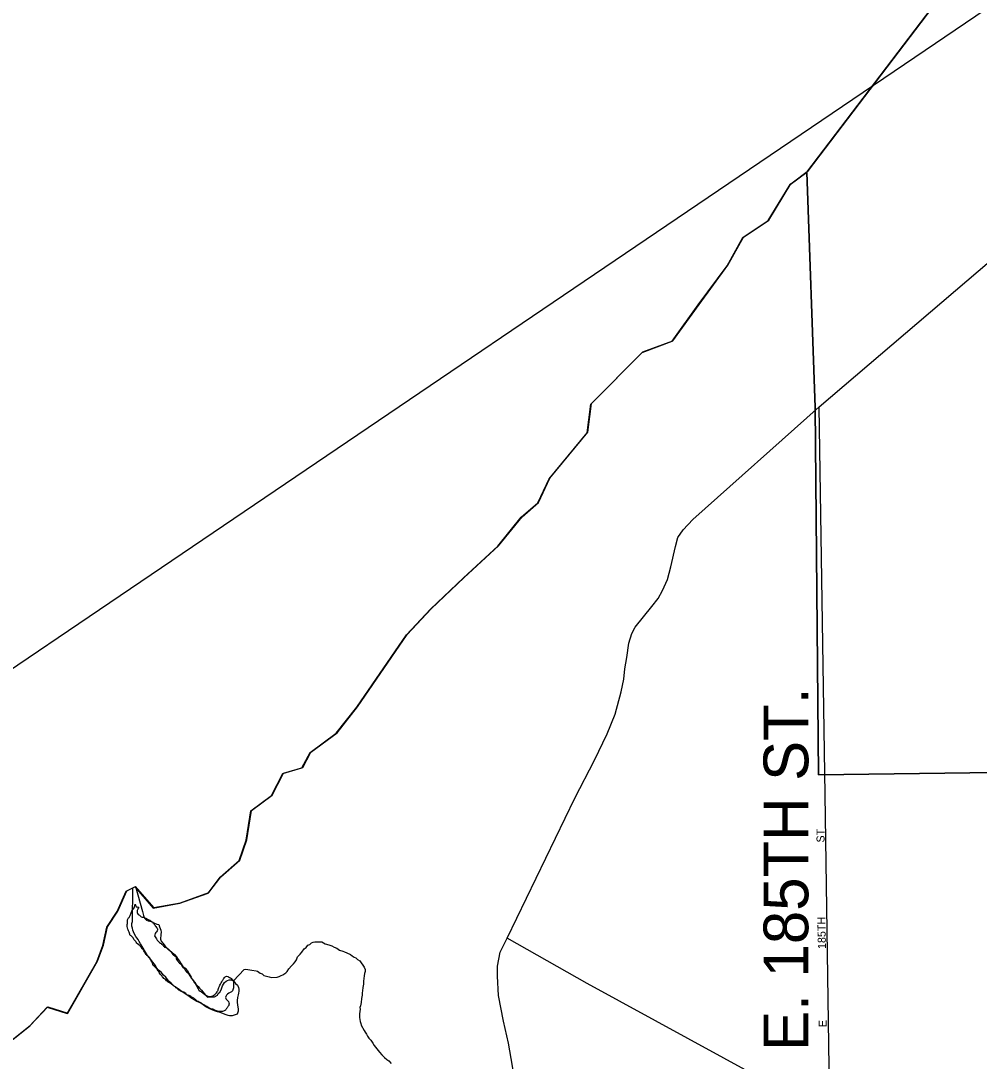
# Model space of a CAD drawing. Extents: x 2139079 to 2262683, y 1235796 to 1334992.
# Drawn here: x 2223564 to 2229551, y 1307072 to 1313569 of the extents above; entities that cross this region are included whole.
import ezdxf

# ---------------------------------------------------------------- set-up
doc = ezdxf.new("R2010")
doc.units = 0
for name, color, linetype in [('GM_X_City_Street', 7, 'Continuous'), ('GM_X_City_Street_Text', 7, 'Continuous'), ('GM_X_Interchange_Ramps', 7, 'Continuous'), ('GM_X_Interstate_Route', 7, 'Continuous'), ('GM_X_Major_Lake', 7, 'Continuous'), ('GM_X_Major_River', 7, 'Continuous'), ('GM_X_Minor_Lake', 7, 'Continuous'), ('GM_X_Minor_River', 7, 'Continuous'), ('GM_X_State_Route', 7, 'Continuous'), ('GM_X_US_Route', 7, 'Continuous')]:
    doc.layers.add(name, color=color, linetype=linetype)

msp = doc.modelspace()

# ---------------------------------------------------------------- linework, layer by layer
at = {"layer": 'GM_X_City_Street'}
for points in [[(2228588, 1308737.8), (2228551.1, 1311159.1)], [(2228627.4, 1305337.6), (2228622.6, 1306468.3), (2228588, 1308737.8)], [(2229151.8, 1305804), (2228622.6, 1306468.3), (2228218.5, 1306943.9), (2228158.5, 1306979.9), (2227102.5, 1307556.5), (2226602.2, 1307841.3)]]:
    msp.add_lwpolyline(points, dxfattribs=at)
at = {"layer": 'GM_X_Interstate_Route'}
for points in [[(2231225.8, 1308895.9), (2228546, 1308860.7), (2228526.3, 1311154.9), (2228474.5, 1312624.7), (2229502.7, 1313976.8)], [(2231225.8, 1308895.9), (2228546, 1308860.7), (2228526.3, 1311154.9), (2228474.5, 1312624.7), (2229502.7, 1313976.8)], [(2223516.6, 1307210.2), (2223618.1, 1307291.6), (2223729.2, 1307409.2), (2223854.1, 1307370.3), (2224039.3, 1307693.4), (2224076.3, 1307794.2), (2224101.2, 1307908.8), (2224166.3, 1308005.9), (2224223.2, 1308132.9), (2224276.7, 1308160.4), (2224390.9, 1308028.3), (2224557.1, 1308058.2), (2224735.1, 1308122.3), (2224810.3, 1308221.4), (2224927.6, 1308325), (2224972.3, 1308451.9), (2225000.5, 1308634.9), (2225129.9, 1308730.6), (2225200.7, 1308867.8), (2225320.7, 1308903.2), (2225371.8, 1309000.1), (2225535.1, 1309120.2), (2225663.8, 1309282.1), (2225974, 1309735), (2226122.8, 1309895.1), (2226329.4, 1310089.9), (2226544, 1310288.9), (2226690.6, 1310469.1), (2226794, 1310558.5), (2226864.6, 1310709.7), (2227102.4, 1310997.2), (2227124.5, 1311176.1), (2227446.2, 1311498.6), (2227632.1, 1311568.8), (2227796.2, 1311795.3), (2227976.2, 1312040), (2228074.7, 1312215.7), (2228232.1, 1312321.7), (2228370.1, 1312547.9), (2228474.5, 1312624.7), (2228526.3, 1311154.9), (2228546, 1308860.7), (2231225.8, 1308895.9)]]:
    msp.add_lwpolyline(points, dxfattribs=at)
at = {"layer": 'GM_X_Major_Lake'}
for points in [[(2224395.3, 1308030.9), (2224561.6, 1308060.8), (2224739.5, 1308124.9), (2224814.7, 1308224), (2224932, 1308327.6), (2224976.8, 1308454.6), (2225004.9, 1308637.5), (2225134.3, 1308733.2), (2225205.1, 1308870.4), (2225325.1, 1308905.8), (2225376.3, 1309002.7), (2225539.6, 1309122.8), (2225668.3, 1309284.7), (2225978.5, 1309737.6), (2226127.3, 1309897.7), (2226333.9, 1310092.6), (2226548.5, 1310291.5), (2226695.1, 1310471.7), (2226798.5, 1310561.1), (2226869.1, 1310712.3), (2227106.8, 1310999.8), (2227129, 1311178.7), (2227450.6, 1311501.2), (2227636.5, 1311571.4), (2227800.6, 1311797.9), (2227980.7, 1312042.7), (2228079.1, 1312218.3), (2228236.5, 1312324.3), (2228374.6, 1312550.6), (2228484, 1312634), (2229507.2, 1313979.4)], [(2223397.7, 1307113.2), (2223521.1, 1307212.8), (2223622.6, 1307294.2), (2223733.7, 1307411.8), (2223858.5, 1307372.9), (2224043.7, 1307696.1), (2224080.7, 1307796.8), (2224105.6, 1307911.5), (2224170.8, 1308008.5), (2224227.6, 1308135.5), (2224281.1, 1308163)], [(2224395.3, 1308030.9), (2224281.1, 1308163)]]:
    msp.add_lwpolyline(points, dxfattribs=at)
at = {"layer": 'GM_X_Major_River'}
for p, q in [((2224278.3, 1308052.4), (2224282.5, 1308040.1)), ((2224282.5, 1308040.1), (2224286, 1308037)), ((2224286, 1308037), (2224289.3, 1308035.2)), ((2224289.3, 1308035.2), (2224294.6, 1308034.1)), ((2224294.6, 1308034.1), (2224302.5, 1308034.6))]:
    msp.add_line(p, q, dxfattribs=at)
for points in [[(2224282.4, 1307819.6), (2224268.2, 1307837.6), (2224262.1, 1307847.6), (2224245.9, 1307861.5), (2224243.8, 1307871.5), (2224237.7, 1307885.5), (2224233.6, 1307897.5), (2224229.5, 1307913.5), (2224229.3, 1307925.6), (2224231.2, 1307939.6), (2224231.1, 1307949.7), (2224233.1, 1307959.7), (2224242.9, 1307973.9), (2224250.8, 1307992), (2224256.7, 1308004.1), (2224260.6, 1308014.2), (2224268.5, 1308024.3), (2224274.5, 1308036.4), (2224278.3, 1308052.4)], [(2224302.5, 1308034.6), (2224290.7, 1308006.4), (2224292.9, 1307994.3), (2224305, 1307984.4), (2224317.1, 1307974.5), (2224329.1, 1307970.6), (2224349.2, 1307962.7), (2224363.3, 1307954.8), (2224375.4, 1307948.8), (2224389.5, 1307936.9), (2224401.6, 1307923), (2224407.7, 1307913), (2224418, 1307891), (2224412, 1307880.9), (2224404.1, 1307868.8), (2224400.2, 1307854.7), (2224408.4, 1307842.7), (2224416.5, 1307828.7), (2224424.6, 1307818.8), (2224436.7, 1307808.8), (2224450.8, 1307796.9), (2224462.9, 1307784.9), (2224477, 1307779), (2224487.1, 1307767.1)], [(2224487.1, 1307767.1), (2224501.3, 1307757.1), (2224509.4, 1307745.1), (2224521.5, 1307731.2), (2224535.6, 1307721.3), (2224535.7, 1307711.2), (2224543.8, 1307699.2), (2224556, 1307683.3), (2224566.1, 1307675.3), (2224574.2, 1307661.4), (2224586.3, 1307649.4), (2224596.5, 1307633.4), (2224608.6, 1307623.5), (2224628.9, 1307591.5), (2224641, 1307577.6), (2224645.1, 1307567.6), (2224655.3, 1307553.6), (2224663.4, 1307539.6), (2224683.7, 1307509.7), (2224693.8, 1307503.7), (2224707.9, 1307491.8), (2224724, 1307481.9), (2224740.1, 1307476), (2224756.1, 1307478.1), (2224770.1, 1307484.3), (2224789.9, 1307504.5), (2224797.8, 1307520.6), (2224801.7, 1307532.7), (2224815.5, 1307560.9), (2224823.4, 1307575), (2224833.3, 1307589.2), (2224841.2, 1307599.3), (2224857.2, 1307601.4), (2224867.2, 1307595.5), (2224881.3, 1307587.5), (2224889.5, 1307575.6), (2224893.6, 1307561.6), (2224893.7, 1307549.5), (2224893.8, 1307537.4), (2224889.9, 1307523.4), (2224886, 1307511.3), (2224872.1, 1307501.1), (2224844.2, 1307476.8), (2224844.4, 1307462.8), (2224856.5, 1307450.8), (2224864.6, 1307436.8), (2224864.7, 1307424.8), (2224854.9, 1307408.6), (2224845, 1307394.5), (2224831, 1307384.4), (2224817, 1307382.2), (2224807, 1307382.2), (2224793, 1307384.1), (2224780.9, 1307388), (2224768.9, 1307393.9), (2224758.8, 1307397.8), (2224744.7, 1307401.7), (2224732.7, 1307409.7), (2224718.6, 1307417.6), (2224708.5, 1307423.5), (2224692.4, 1307433.4), (2224678.3, 1307441.4), (2224666.2, 1307447.3), (2224656.1, 1307457.2), (2224640, 1307467.1), (2224625.9, 1307477.1), (2224615.8, 1307483), (2224603.8, 1307484.9), (2224595.7, 1307494.9), (2224567.5, 1307506.7), (2224557.5, 1307512.6), (2224547.4, 1307520.6), (2224523.2, 1307540.5), (2224513.1, 1307546.4), (2224503, 1307554.4), (2224484.9, 1307566.3), (2224474.8, 1307574.2), (2224464.7, 1307584.2), (2224452.6, 1307594.1), (2224442.5, 1307608.1), (2224432.3, 1307620.1), (2224426.2, 1307632.1), (2224418.1, 1307642), (2224403.9, 1307660), (2224391.8, 1307669.9), (2224387.7, 1307683.9), (2224379.6, 1307697.9), (2224371.4, 1307713.9), (2224363.3, 1307723.9), (2224349.2, 1307735.8), (2224339.1, 1307749.8), (2224332.9, 1307761.8), (2224322.8, 1307775.8), (2224312.7, 1307787.7), (2224300.6, 1307799.7), (2224288.5, 1307809.6), (2224282.4, 1307819.6)]]:
    msp.add_spline(points, degree=3, dxfattribs=at)
at = {"layer": 'GM_X_Minor_Lake'}
for points in [[(2224281.1, 1308163), (2224325.5, 1308007.1), (2224325.7, 1307999.1), (2224330, 1307981.1), (2224336.4, 1307965.1), (2224348.7, 1307953.3), (2224360.8, 1307949.5), (2224370.9, 1307945.7), (2224385, 1307942), (2224395.2, 1307936.1), (2224413.4, 1307928.5), (2224427.6, 1307924.7), (2224429.9, 1307910.7), (2224438.3, 1307890.8), (2224440.6, 1307878.8), (2224438.9, 1307862.6), (2224437.4, 1307834.5), (2224441.7, 1307822.5), (2224452, 1307808.7), (2224466.4, 1307790.9), (2224476.7, 1307779), (2224523.8, 1307737.7), (2224536.1, 1307723.9), (2224546.5, 1307708), (2224556.8, 1307694.2), (2224567.1, 1307680.3), (2224577.5, 1307664.4), (2224591.8, 1307652.6), (2224606.1, 1307636.9), (2224616.6, 1307617), (2224622.8, 1307607.1), (2224629, 1307597.1), (2224633.3, 1307587.2), (2224639.5, 1307577.2), (2224651.8, 1307563.4), (2224658, 1307553.5), (2224672.4, 1307537.7), (2224680.7, 1307527.8), (2224692.9, 1307516), (2224701.2, 1307506.1), (2224709.5, 1307494.2), (2224719.7, 1307482.4), (2224730, 1307472.5), (2224758.1, 1307473.1), (2224774.1, 1307473.4), (2224792, 1307483.8), (2224797.8, 1307493.9), (2224807.6, 1307504.1), (2224815.4, 1307518.3), (2224824.9, 1307542.6), (2224830.7, 1307552.8), (2224836.6, 1307563), (2224846.4, 1307571.2), (2224856.4, 1307575.4), (2224866.3, 1307579.6), (2224878.4, 1307579.8), (2224892.6, 1307574.1), (2224904.9, 1307558.2), (2224917.2, 1307546.4), (2224923.5, 1307532.5), (2224925.7, 1307522.5), (2224926, 1307510.4), (2224924.3, 1307496.3), (2224922.5, 1307486.3), (2224918.8, 1307470.1), (2224915.1, 1307452), (2224915.4, 1307437.9), (2224917.7, 1307423.9), (2224920, 1307409.9), (2224922.2, 1307399.9), (2224922.5, 1307383.8), (2224914.9, 1307365.6), (2224896.9, 1307359.2), (2224885, 1307355), (2224868.9, 1307354.7), (2224858.9, 1307356.5), (2224846.7, 1307362.3), (2224830.5, 1307368), (2224816.3, 1307373.7), (2224804.2, 1307377.5), (2224792.1, 1307381.3), (2224773.9, 1307387), (2224759.7, 1307392.7), (2224745.5, 1307398.5), (2224733.4, 1307404.3), (2224719.2, 1307412), (2224702.9, 1307423.8), (2224684.5, 1307435.5), (2224664.3, 1307445.1), (2224648, 1307454.9), (2224631.7, 1307464.6), (2224615.4, 1307476.3), (2224591, 1307491.9), (2224572.7, 1307505.6), (2224556.4, 1307517.4), (2224540.1, 1307529.1), (2224523.8, 1307538.8), (2224513.6, 1307548.7), (2224503.3, 1307558.5), (2224491, 1307570.4), (2224480.7, 1307582.2)], [(2224315.8, 1307797.8), (2224311.5, 1307806), (2224303.2, 1307819.8), (2224296.9, 1307831.8), (2224288.7, 1307841.7), (2224282.5, 1307851.6), (2224272.1, 1307869.5), (2224267.9, 1307879.4), (2224263.6, 1307889.4), (2224261.3, 1307903.4), (2224257.1, 1307915.4), (2224258.8, 1307931.5), (2224262.5, 1307943.6), (2224264.4, 1308152.6)], [(2224480.7, 1307582.2), (2224470.4, 1307596.1), (2224456.1, 1307609.9), (2224441.7, 1307627.7), (2224425.3, 1307641.4), (2224415, 1307653.3), (2224406.8, 1307665.2), (2224398.5, 1307677.1), (2224388.2, 1307690.9), (2224375.8, 1307706.8), (2224365.5, 1307720.6), (2224355.2, 1307732.5), (2224315.8, 1307797.8)]]:
    msp.add_lwpolyline(points, dxfattribs=at)
at = {"layer": 'GM_X_Minor_River'}
msp.add_lwpolyline([(2224892.6, 1307574.1), (2224959.4, 1307645.7), (2224969.4, 1307645.9), (2224983.5, 1307644.1), (2225007.7, 1307640.6), (2225033.8, 1307637.1), (2225043.9, 1307633.3), (2225060.3, 1307621.5), (2225072.4, 1307617.7), (2225082.6, 1307607.9), (2225098.8, 1307602.2), (2225114.9, 1307598.5), (2225131.1, 1307594.8), (2225165.2, 1307597.4), (2225179.1, 1307601.7), (2225191.1, 1307608), (2225201, 1307612.2), (2225218.8, 1307624.6), (2225228.7, 1307632.8), (2225238.4, 1307649.1), (2225256.1, 1307667.5), (2225267.9, 1307679.8), (2225277.7, 1307692), (2225285.5, 1307704.2), (2225293.1, 1307724.4), (2225308.8, 1307740.8), (2225320.6, 1307753.1), (2225334.3, 1307773.5), (2225346.1, 1307781.7), (2225357.9, 1307796), (2225369.9, 1307800.3), (2225379.7, 1307810.5), (2225389.6, 1307814.7), (2225401.6, 1307816.9), (2225415.7, 1307817.2), (2225433.7, 1307817.6), (2225443.8, 1307817.8), (2225466.2, 1307804.1), (2225488.4, 1307798.5), (2225506.5, 1307792.8), (2225520.8, 1307785.1), (2225539, 1307777.4), (2225555.3, 1307765.7), (2225575.5, 1307760), (2225585.6, 1307754.2), (2225601.8, 1307748.5), (2225624.1, 1307738.9), (2225634.3, 1307731), (2225646.6, 1307721.2), (2225656.7, 1307717.4), (2225666.9, 1307707.6), (2225681.2, 1307697.8), (2225689.5, 1307685.9), (2225701.8, 1307672.1), (2225710.1, 1307660.2), (2225714.4, 1307644.2), (2225714.6, 1307632.1), (2225710.9, 1307620), (2225709.2, 1307605.9), (2225707.5, 1307587.8), (2225705.8, 1307571.7), (2225704.2, 1307553.6), (2225700.6, 1307531.4), (2225699, 1307511.3), (2225697.3, 1307499.2), (2225695.6, 1307485.1), (2225693.8, 1307475), (2225692, 1307463), (2225690.5, 1307438.8), (2225686.9, 1307418.7), (2225683.1, 1307406.5), (2225683.3, 1307396.5), (2225681.6, 1307382.4), (2225679.9, 1307368.3), (2225680.1, 1307356.3), (2225680.4, 1307344.2), (2225682.6, 1307332.2), (2225684.9, 1307320.2), (2225689.1, 1307308.2), (2225691.4, 1307296.2), (2225708.1, 1307264.4), (2225716.4, 1307252.5), (2225724.7, 1307240.6), (2225730.9, 1307228.7), (2225739.2, 1307216.8), (2225751.5, 1307202.9), (2225763.9, 1307185.1), (2225772.3, 1307169.2), (2225788.8, 1307149.4), (2225805.3, 1307127.6), (2225819.6, 1307111.8), (2225836, 1307096.1), (2225850.4, 1307082.3), (2225862.6, 1307074.5), (2225877, 1307056.7)], dxfattribs=at)
at = {"layer": 'GM_X_State_Route'}
for points in [[(2228551.1, 1311159.1), (2231161.4, 1313386.3), (2233896.5, 1315721.3)], [(2226639, 1307015.8), (2226627.7, 1307088.5), (2226610.3, 1307183.8), (2226578.8, 1307322.5), (2226548.4, 1307482.6), (2226542.6, 1307602.9), (2226541.4, 1307666), (2226557.8, 1307753.6), (2226602.2, 1307841.3), (2227025.9, 1308714.2), (2227148.7, 1308951.7), (2227226.3, 1309116.8), (2227277.3, 1309239), (2227313.8, 1309377.7), (2227330.3, 1309457.9), (2227337.9, 1309522.9), (2227350.3, 1309593), (2227363.1, 1309682.4), (2227381, 1309742.9), (2227401.4, 1309781.8), (2227505.7, 1309912), (2227546, 1309960.8), (2227572.3, 1310011.9), (2227603.4, 1310081), (2227625, 1310158.8), (2227653.1, 1310286.3), (2227668.9, 1310342.3), (2227701.4, 1310391.1), (2227761.1, 1310454.4), (2228551.1, 1311159.1)]]:
    msp.add_lwpolyline(points, dxfattribs=at)
at = {"layer": 'GM_X_US_Route'}
msp.add_lwpolyline([(2202867.6, 1295541.4), (2210353.6, 1284489.3), (2249318.3, 1310881.6), (2241832.3, 1321933.6)], close=True, dxfattribs=at)

# ---------------------------------------------------------------- texts
at = {"layer": 'GM_X_City_Street_Text'}
for s, rotation, p in [('ST', 90, (2228584.7, 1308437.8)), ('185TH', 91.16851, (2228593.5, 1307773.2)), ('E', 90, (2228597.9, 1307285))]:
    msp.add_text(s, height=50, rotation=rotation, dxfattribs=at).set_placement(p)
at = {"layer": 'GM_X_Interchange_Ramps'}
msp.add_text('E. 185TH ST.', height=280, rotation=90, dxfattribs=at).set_placement((2228483.5, 1307137))

doc.saveas('drawing.dxf')
